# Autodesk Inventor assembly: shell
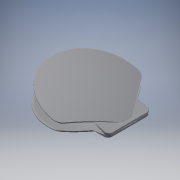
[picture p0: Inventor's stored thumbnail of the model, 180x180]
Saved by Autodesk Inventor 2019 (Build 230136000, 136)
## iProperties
Created: 2021-03
Part Number: shell
Material: 一般
Document SubType Name: Assembly
Designer: kikut
Author: kikut
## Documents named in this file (2)
- F:\openFOAM\shell\shell00\cad\shell.iam
- F:\openFOAM\shell\shell00\cad\shell180deg.iam
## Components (1 placed, 1 different names)
1. shell180deg:1 [sub-assembly]
